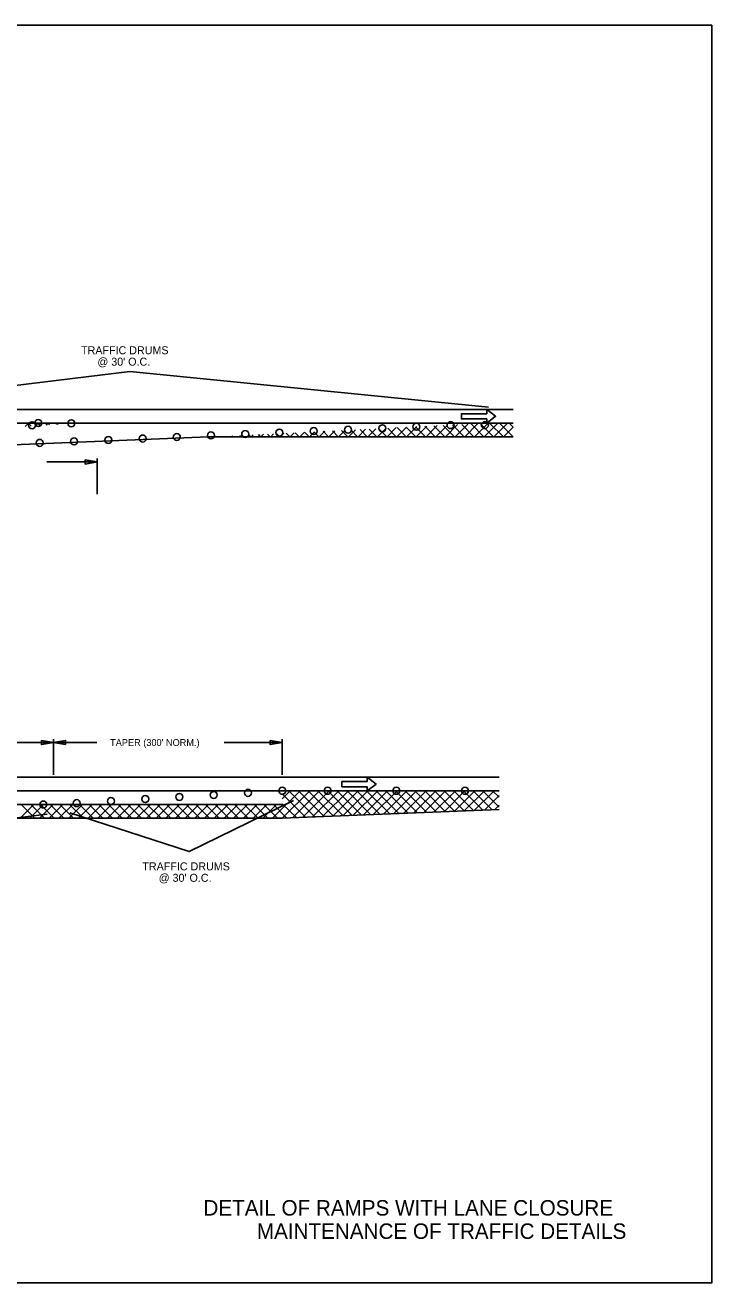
# Model space of a CAD drawing. Extents: x 1374027 to 1374537, y 380415 to 381405.
# Drawn here: x 1374477.1 to 1374537.1, y 380635.2 to 380745.2 of the extents above; entities that cross this region are included whole.
import ezdxf

# ---------------------------------------------------------------- set-up
doc = ezdxf.new("R2010")
doc.units = 0
for name, color, linetype in [('Default', 7, 'Continuous'), ('DSN_DRFT_Junk-No-Plot', 7, 'Continuous'), ('Edge of Lanes', 7, 'Continuous'), ('Level 1', 7, 'Continuous'), ('Level 40', 7, 'Continuous'), ('NOTES', 7, 'Continuous'), ('R_Border Notes', 7, 'Continuous')]:
    doc.layers.add(name, color=color, linetype=linetype)

msp = doc.modelspace()

# ---------------------------------------------------------------- linework, layer by layer
at = {"layer": 'Default'}
for points in [[(1374517.4, 380710.37), (1374518.18, 380710.97), (1374517.4, 380711.57), (1374517.4, 380711.19), (1374515.19, 380711.19), (1374515.19, 380710.74), (1374517.4, 380710.74)], [(1374506.95, 380678.2), (1374507.73, 380678.8), (1374506.95, 380679.4), (1374506.95, 380679.02), (1374504.75, 380679.02), (1374504.75, 380678.57), (1374506.95, 380678.57)]]:
    msp.add_lwpolyline(points, close=True, dxfattribs=at)
at = {"layer": 'DSN_DRFT_Junk-No-Plot'}
for points in [[(1374367.08, 380745.17), (1374537.08, 380745.17), (1374537.08, 380635.17), (1374367.08, 380635.17)], [(1374367.08, 380745.17), (1374367.08, 380635.17), (1374537.08, 380635.17), (1374537.08, 380745.17)]]:
    msp.add_lwpolyline(points, close=True, dxfattribs=at)
at = {"layer": 'Edge of Lanes'}
for p, q in [((1374519.71, 380711.56), (1374379.75, 380711.56)), ((1374519.71, 380710.36), (1374379.75, 380710.36)), ((1374477.06, 380710.08), (1374477.33, 380710.36)), ((1374477.33, 380710.36), (1374477.58, 380710.11)), ((1374477.97, 380710.14), (1374478.18, 380710.36)), ((1374478.18, 380710.36), (1374478.37, 380710.17)), ((1374478.88, 380710.2), (1374479.03, 380710.36)), ((1374479.03, 380710.36), (1374479.17, 380710.22)), ((1374479.78, 380710.26), (1374479.88, 380710.36)), ((1374479.88, 380710.36), (1374479.96, 380710.27)), ((1374480.69, 380710.32), (1374480.73, 380710.36)), ((1374480.73, 380710.36), (1374480.76, 380710.32)), ((1374509.52, 380709.15), (1374510.39, 380710.01)), ((1374510.37, 380709.15), (1374511.28, 380710.06)), ((1374510.37, 380710.01), (1374511.23, 380709.15)), ((1374511.18, 380710.05), (1374512.08, 380709.15)), ((1374511.22, 380709.15), (1374512.17, 380710.1)), ((1374511.99, 380710.09), (1374512.93, 380709.15)), ((1374512.07, 380709.15), (1374513.07, 380710.15)), ((1374512.79, 380710.13), (1374513.77, 380709.15)), ((1374512.92, 380709.15), (1374513.96, 380710.19)), ((1374513.6, 380710.17), (1374514.62, 380709.15)), ((1374513.77, 380709.15), (1374514.85, 380710.24)), ((1374514.41, 380710.21), (1374515.47, 380709.15)), ((1374514.62, 380709.15), (1374515.75, 380710.28)), ((1374515.22, 380710.25), (1374516.32, 380709.15)), ((1374515.47, 380709.15), (1374516.64, 380710.33)), ((1374516.03, 380710.29), (1374517.17, 380709.15)), ((1374516.32, 380709.15), (1374517.52, 380710.36)), ((1374516.83, 380710.34), (1374518.02, 380709.15)), ((1374517.16, 380709.15), (1374518.37, 380710.36)), ((1374517.66, 380710.36), (1374518.86, 380709.16)), ((1374518.01, 380709.15), (1374519.21, 380710.36)), ((1374518.51, 380710.36), (1374519.71, 380709.16)), ((1374518.86, 380709.16), (1374519.71, 380710)), ((1374519.36, 380710.36), (1374519.71, 380710)), ((1374463.04, 380707.96), (1374493.04, 380709.16)), ((1374519.71, 380709.16), (1374493.04, 380709.16)), ((1374493.39, 380709.14), (1374493.41, 380709.16)), ((1374493.4, 380709.16), (1374493.42, 380709.14)), ((1374494.21, 380709.2), (1374494.27, 380709.14)), ((1374494.24, 380709.14), (1374494.31, 380709.21)), ((1374495.02, 380709.24), (1374495.12, 380709.14)), ((1374495.09, 380709.14), (1374495.2, 380709.25)), ((1374495.83, 380709.28), (1374495.96, 380709.14)), ((1374495.94, 380709.14), (1374496.09, 380709.3)), ((1374496.63, 380709.32), (1374496.81, 380709.14)), ((1374496.79, 380709.14), (1374496.99, 380709.34)), ((1374497.44, 380709.36), (1374497.66, 380709.14)), ((1374497.64, 380709.14), (1374497.88, 380709.39)), ((1374498.25, 380709.4), (1374498.51, 380709.14)), ((1374498.49, 380709.14), (1374498.77, 380709.43)), ((1374499.06, 380709.44), (1374499.36, 380709.15)), ((1374499.34, 380709.15), (1374499.67, 380709.48)), ((1374499.87, 380709.49), (1374500.21, 380709.15)), ((1374500.19, 380709.15), (1374500.56, 380709.52)), ((1374500.67, 380709.53), (1374501.05, 380709.15)), ((1374501.03, 380709.15), (1374501.45, 380709.56)), ((1374501.48, 380709.57), (1374501.9, 380709.15)), ((1374501.88, 380709.15), (1374502.35, 380709.61)), ((1374502.29, 380709.61), (1374502.75, 380709.15)), ((1374502.73, 380709.15), (1374503.24, 380709.65)), ((1374503.1, 380709.65), (1374503.6, 380709.15)), ((1374503.58, 380709.15), (1374504.13, 380709.7)), ((1374503.91, 380709.69), (1374504.45, 380709.15)), ((1374504.43, 380709.15), (1374505.03, 380709.74)), ((1374504.71, 380709.73), (1374505.29, 380709.15)), ((1374505.28, 380709.15), (1374505.92, 380709.79)), ((1374505.52, 380709.77), (1374506.14, 380709.15)), ((1374506.13, 380709.15), (1374506.81, 380709.83)), ((1374506.33, 380709.81), (1374506.99, 380709.15)), ((1374506.98, 380709.15), (1374507.71, 380709.88)), ((1374507.14, 380709.85), (1374507.84, 380709.15)), ((1374507.83, 380709.15), (1374508.6, 380709.92)), ((1374507.95, 380709.89), (1374508.69, 380709.15)), ((1374508.68, 380709.15), (1374509.49, 380709.97)), ((1374508.75, 380709.93), (1374509.53, 380709.15)), ((1374509.56, 380709.97), (1374510.38, 380709.15)), ((1374518.49, 380679.41), (1374388.51, 380679.41)), ((1374518.49, 380678.21), (1374388.51, 380678.21)), ((1374498.68, 380675.81), (1374501.08, 380678.21)), ((1374499.53, 380675.81), (1374501.93, 380678.21)), ((1374499.53, 380677.51), (1374500.23, 380678.21)), ((1374500.1, 380678.21), (1374502.39, 380675.92)), ((1374500.41, 380675.85), (1374502.78, 380678.21)), ((1374500.95, 380678.21), (1374503.2, 380675.96)), ((1374501.3, 380675.88), (1374503.63, 380678.21)), ((1374501.8, 380678.21), (1374504.02, 380675.99)), ((1374502.18, 380675.92), (1374504.47, 380678.21)), ((1374502.65, 380678.21), (1374504.84, 380676.02)), ((1374503.06, 380675.95), (1374505.32, 380678.21)), ((1374503.5, 380678.21), (1374505.65, 380676.05)), ((1374503.95, 380675.99), (1374506.17, 380678.21)), ((1374504.34, 380678.21), (1374506.47, 380676.09)), ((1374504.83, 380676.02), (1374507.02, 380678.21)), ((1374505.19, 380678.21), (1374507.28, 380676.12)), ((1374505.71, 380676.06), (1374507.87, 380678.21)), ((1374506.04, 380678.21), (1374508.1, 380676.15)), ((1374506.6, 380676.09), (1374508.72, 380678.21)), ((1374506.89, 380678.21), (1374508.92, 380676.19)), ((1374507.48, 380676.13), (1374509.57, 380678.21)), ((1374507.74, 380678.21), (1374509.73, 380676.22)), ((1374508.37, 380676.16), (1374510.41, 380678.21)), ((1374508.59, 380678.21), (1374510.55, 380676.25)), ((1374509.25, 380676.2), (1374511.26, 380678.21)), ((1374509.44, 380678.21), (1374511.36, 380676.28)), ((1374510.13, 380676.23), (1374512.11, 380678.21)), ((1374510.28, 380678.21), (1374512.18, 380676.32)), ((1374511.02, 380676.27), (1374512.96, 380678.21)), ((1374511.13, 380678.21), (1374513, 380676.35)), ((1374511.9, 380676.3), (1374513.81, 380678.21)), ((1374511.98, 380678.21), (1374513.81, 380676.38)), ((1374512.79, 380676.34), (1374514.66, 380678.21)), ((1374512.83, 380678.21), (1374514.63, 380676.41)), ((1374513.67, 380676.38), (1374515.5, 380678.21)), ((1374513.68, 380678.21), (1374515.44, 380676.45)), ((1374514.53, 380678.21), (1374516.26, 380676.48)), ((1374514.55, 380676.41), (1374516.35, 380678.21)), ((1374515.38, 380678.21), (1374517.07, 380676.51)), ((1374515.44, 380676.45), (1374517.2, 380678.21)), ((1374516.22, 380678.21), (1374517.89, 380676.54)), ((1374516.32, 380676.48), (1374518.05, 380678.21)), ((1374517.07, 380678.21), (1374518.49, 380676.79)), ((1374517.92, 380678.21), (1374518.49, 380677.64)), ((1374499.53, 380677.01), (1374429.42, 380677.01)), ((1374476.62, 380675.81), (1374477.82, 380677.01)), ((1374476.7, 380677.01), (1374477.9, 380675.81)), ((1374477.47, 380675.81), (1374478.67, 380677.01)), ((1374477.54, 380677.01), (1374478.74, 380675.81)), ((1374478.31, 380675.81), (1374479.51, 380677.01)), ((1374478.39, 380677.01), (1374479.59, 380675.81)), ((1374479.16, 380675.81), (1374480.36, 380677.01)), ((1374479.24, 380677.01), (1374480.44, 380675.81)), ((1374480.01, 380675.81), (1374481.21, 380677.01)), ((1374480.09, 380677.01), (1374481.29, 380675.81)), ((1374480.86, 380675.81), (1374482.06, 380677.01)), ((1374480.94, 380677.01), (1374482.14, 380675.81)), ((1374481.71, 380675.81), (1374482.91, 380677.01)), ((1374481.79, 380677.01), (1374482.99, 380675.81)), ((1374482.56, 380675.81), (1374483.76, 380677.01)), ((1374482.64, 380677.01), (1374483.84, 380675.81)), ((1374483.41, 380675.81), (1374484.61, 380677.01)), ((1374483.48, 380677.01), (1374484.68, 380675.81)), ((1374484.25, 380675.81), (1374485.45, 380677.01)), ((1374484.33, 380677.01), (1374485.53, 380675.81)), ((1374485.1, 380675.81), (1374486.3, 380677.01)), ((1374485.18, 380677.01), (1374486.38, 380675.81)), ((1374485.95, 380675.81), (1374487.15, 380677.01)), ((1374486.03, 380677.01), (1374487.23, 380675.81)), ((1374486.8, 380675.81), (1374488, 380677.01)), ((1374486.88, 380677.01), (1374488.08, 380675.81)), ((1374487.65, 380675.81), (1374488.85, 380677.01)), ((1374487.73, 380677.01), (1374488.93, 380675.81)), ((1374488.5, 380675.81), (1374489.7, 380677.01)), ((1374488.58, 380677.01), (1374489.78, 380675.81)), ((1374489.35, 380675.81), (1374490.55, 380677.01)), ((1374489.42, 380677.01), (1374490.62, 380675.81)), ((1374490.19, 380675.81), (1374491.39, 380677.01)), ((1374490.27, 380677.01), (1374491.47, 380675.81)), ((1374491.04, 380675.81), (1374492.24, 380677.01)), ((1374491.12, 380677.01), (1374492.32, 380675.81)), ((1374491.89, 380675.81), (1374493.09, 380677.01)), ((1374491.97, 380677.01), (1374493.17, 380675.81)), ((1374492.74, 380675.81), (1374493.94, 380677.01)), ((1374492.82, 380677.01), (1374494.02, 380675.81)), ((1374493.59, 380675.81), (1374494.79, 380677.01)), ((1374493.67, 380677.01), (1374494.87, 380675.81)), ((1374494.44, 380675.81), (1374495.64, 380677.01)), ((1374494.51, 380677.01), (1374495.71, 380675.81)), ((1374495.28, 380675.81), (1374496.48, 380677.01)), ((1374495.36, 380677.01), (1374496.56, 380675.81)), ((1374496.13, 380675.81), (1374497.33, 380677.01)), ((1374496.21, 380677.01), (1374497.41, 380675.81)), ((1374496.98, 380675.81), (1374498.18, 380677.01)), ((1374497.06, 380677.01), (1374498.26, 380675.81)), ((1374497.83, 380675.81), (1374499.03, 380677.01)), ((1374497.91, 380677.01), (1374499.11, 380675.81)), ((1374498.76, 380677.01), (1374499.94, 380675.83)), ((1374499.53, 380677.94), (1374501.57, 380675.89)), ((1374499.53, 380677.08), (1374500.76, 380675.86)), ((1374517.21, 380676.52), (1374518.49, 380677.8)), ((1374499.53, 380675.81), (1374518.49, 380676.57)), ((1374518.09, 380676.55), (1374518.49, 380676.96)), ((1374499.53, 380675.81), (1374432.52, 380675.81))]:
    msp.add_line(p, q, dxfattribs=at)
at = {"layer": 'Level 1'}
for points in [[(1374517.55, 380711.75), (1374486.2, 380714.89), (1374461.85, 380711.9)], [(1374480.97, 380676.27), (1374491.4, 380672.89), (1374500.52, 380677.37)], [(1374431.17, 380675.58), (1374452.28, 380672.89), (1374478.97, 380676.16)]]:
    msp.add_lwpolyline(points, dxfattribs=at)
at = {"layer": 'Level 40'}
for centre in [(1374477.66, 380710.18), (1374478.2, 380710.37), (1374481.09, 380710.35), (1374505.28, 380709.79), (1374508.28, 380709.92), (1374511.26, 380710.05), (1374514.24, 380710.19), (1374517.24, 380710.19), (1374478.33, 380708.64), (1374481.33, 380708.77), (1374484.33, 380708.89), (1374487.33, 380709.02), (1374490.31, 380709.15), (1374493.29, 380709.29), (1374496.29, 380709.41), (1374499.28, 380709.54), (1374502.28, 380709.67), (1374493.54, 380677.85), (1374496.53, 380678.03), (1374499.53, 380678.21), (1374503.5, 380678.21), (1374509.5, 380678.21), (1374515.5, 380678.21), (1374478.64, 380677.01), (1374481.56, 380677.13), (1374484.55, 380677.31), (1374487.55, 380677.49), (1374490.54, 380677.67)]:
    msp.add_circle(centre, 0.305, dxfattribs=at)
at = {"layer": 'NOTES'}
for p, q in [((1374483.34, 380706.98), (1374478.94, 380706.98)), ((1374483.34, 380704.15), (1374483.34, 380707.28)), ((1374479.53, 380679.61), (1374479.53, 380682.73)), ((1374479.53, 380679.61), (1374479.53, 380682.73)), ((1374499.53, 380679.61), (1374499.53, 380682.73)), ((1374462.01, 380682.43), (1374479.53, 380682.43)), ((1374483.32, 380682.43), (1374479.53, 380682.43)), ((1374494.45, 380682.43), (1374499.53, 380682.43))]:
    msp.add_line(p, q, dxfattribs=at)
for points in [[(1374482.29, 380707.16), (1374483.34, 380706.98), (1374482.29, 380706.79)], [(1374478.48, 380682.62), (1374479.53, 380682.43), (1374478.48, 380682.25)], [(1374480.58, 380682.25), (1374479.53, 380682.43), (1374480.58, 380682.62)], [(1374498.48, 380682.62), (1374499.53, 380682.43), (1374498.48, 380682.25)]]:
    msp.add_lwpolyline(points, close=True, dxfattribs=at)

# ---------------------------------------------------------------- texts
at = {"layer": 'Level 1'}
for s, p in [('TRAFFIC DRUMS', (1374481.94, 380716.39)), ("@ 30' O.C.", (1374483.37, 380715.39)), ('TRAFFIC DRUMS', (1374487.3, 380671.25)), ("@ 30' O.C.", (1374488.73, 380670.25))]:
    msp.add_text(s, height=0.7, rotation=360, dxfattribs=at).set_placement(p)
at = {"layer": 'NOTES'}
msp.add_text("TAPER (300' NORM.)", height=0.6, dxfattribs=at).set_placement((1374484.48, 380682.13))
at = {"layer": 'R_Border Notes'}
for s, p in [('DETAIL OF RAMPS WITH LANE CLOSURE', (1374492.64, 380641.06)), ('MAINTENANCE OF TRAFFIC DETAILS', (1374497.31, 380639.02))]:
    msp.add_text(s, height=1.35, dxfattribs=at).set_placement(p)

doc.saveas('drawing.dxf')
